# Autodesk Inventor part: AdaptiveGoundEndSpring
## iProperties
Shininess: 64.0
Angle Display Precision: 2
Document Length Units: 11272
Document Angle Units: 11279
Document Time Units: 11290
Document Mass Units: 11286
Document Length Units Precision: 3
Document Angle Units Precision: 2
Compacted: True
Part Number: AdaptiveGoundEndSpring
Document SubType Name: Modeling
Material: Stainless Steel, Austenitic
Created: 2005-07
Designer: CBliss
Manufacturer: Standard
Standards Organization: Custom
Catalog Web Link: http://www.cbliss.com/inventor
Density: 0.0
Volumn: 0.0
Area: 0.0
PropertySet Name: Model Information
Control State: 0
Master: False
Checked Out: False
Author: CBliss
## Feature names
1. Coil2
2. Extrusion3
3. Extrusion5
